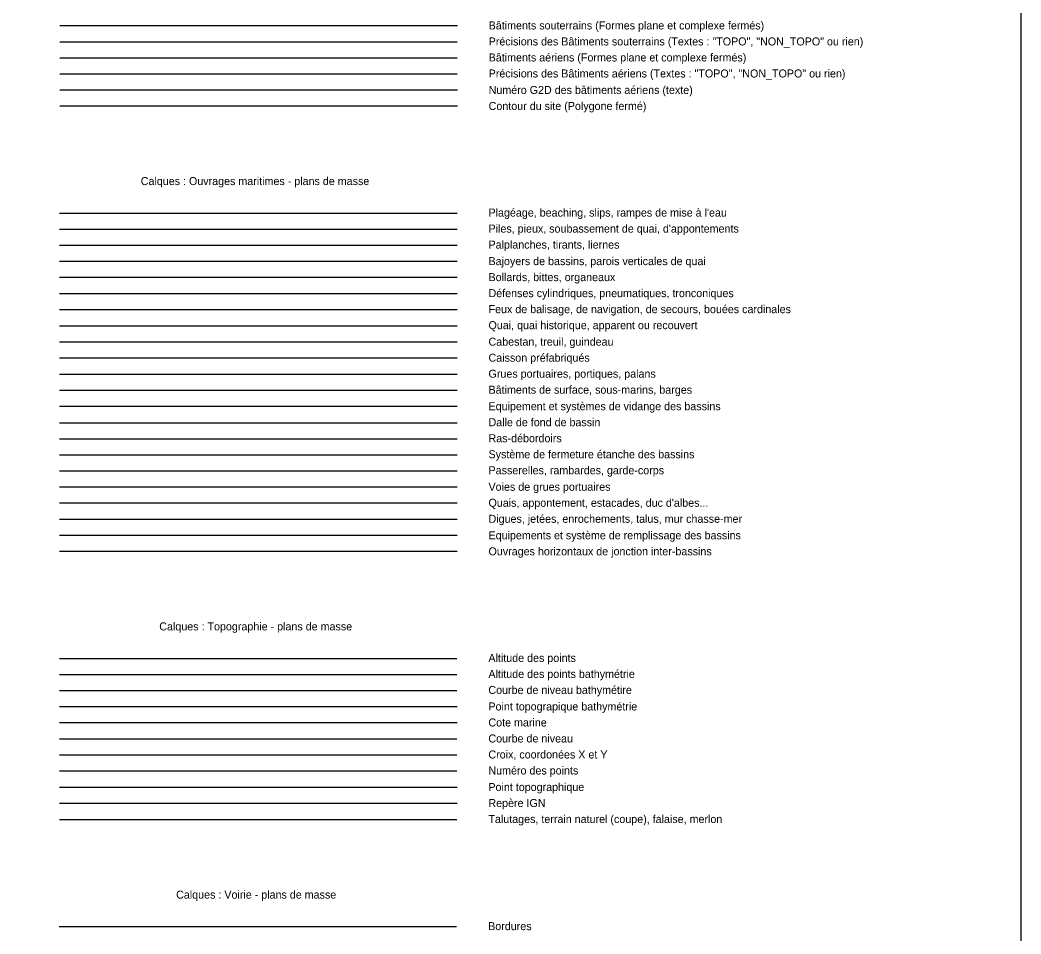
# Model space of a CAD drawing. Extents: x 703432 to 707394, y 7057985 to 7059523.
# Drawn here: x 707262 to 707324.5, y 7058477.4 to 7058534.5 of the extents above; entities that cross this region are included whole.
import ezdxf

# ---------------------------------------------------------------- set-up
doc = ezdxf.new("R2010")
doc.units = 0
for name, color, linetype in [('DH_CADRE -CARTOUCHE', 7, 'Continuous'), ('GEOSID_BATI_AERIEN _POLYGONE', 7, 'Continuous'), ('GEOSID_BATI_AERIEN_NUMERO', 7, 'Continuous'), ('GEOSID_BATI_AERIEN_PRECISION', 7, 'Continuous'), ('GEOSID_BATI_SOUTERRAIN_POLYGONE', 7, 'Continuous'), ('GEOSID_BATI_SOUTERRAIN_PRECISION', 7, 'Continuous'), ('GEOSID_SITE_POLYGONE', 7, 'Continuous'), ('OM_BAJOYER', 7, 'Continuous'), ('OM_BATEAU PORTE', 7, 'Continuous'), ('OM_BOLLARDS', 7, 'Continuous'), ('OM_CABESTAN', 7, 'Continuous'), ('OM_CAISSON PREFA', 7, 'Continuous'), ('OM_CONSTRUCTION METAL', 7, 'Continuous'), ('OM_DEFENSE D ACCOSTAGE', 7, 'Continuous'), ('OM_EQUIP DE LEVAGE', 7, 'Continuous'), ('OM_GALERIE REFOULEMENT', 7, 'Continuous'), ('OM_NAVIRE', 7, 'Continuous'), ('OM_OUVRAGES DE PROTECTION', 7, 'Continuous'), ('OM_OUVRAGES D’ACCOSTAGE', 7, 'Continuous'), ('OM_PAL TIR LIER', 7, 'Continuous'), ('OM_PLAGEAGE', 7, 'Continuous'), ('OM_QUAI', 7, 'Continuous'), ('OM_RADIER', 7, 'Continuous'), ('OM_RAS DEBORDOIR', 7, 'Continuous'), ('OM_SIGNAL NAUTIQUE', 7, 'Continuous'), ('OM_SOUBASSEMENT', 7, 'Continuous'), ('OM_STATION DE POMPAGE', 7, 'Continuous'), ('OM_TERRE-PLEINS', 7, 'Continuous'), ('OM_VOIES DE GRUES', 7, 'Continuous'), ('TOPO_ALT POINT', 7, 'Continuous'), ('TOPO_BATHY ALT COURBE NIVEAU', 7, 'Continuous'), ('TOPO_BATHY ALT POINT', 7, 'Continuous'), ('TOPO_BATHYMETRIE', 7, 'Continuous'), ('TOPO_COTE MARINE', 7, 'Continuous'), ('TOPO_COURBE NIVEAU', 7, 'Continuous'), ('TOPO_CROIX COORDONNEE', 7, 'Continuous'), ('TOPO_NUM POINT', 7, 'Continuous'), ('TOPO_POINT', 7, 'Continuous'), ('TOPO_REPERE IGN', 7, 'Continuous'), ('TOPO_TALUS-TERRAIN', 7, 'Continuous'), ('VOIRIE BORDURE', 7, 'Continuous')]:
    doc.layers.add(name, color=color, linetype=linetype)

msp = doc.modelspace()

# ---------------------------------------------------------------- linework, layer by layer
at = {"layer": 'DH_CADRE -CARTOUCHE'}
msp.add_lwpolyline([(707199.469, 7058644.551), (707324.469, 7058644.551), (707324.469, 7058419.551), (707199.469, 7058419.551)], close=True, dxfattribs=at)
at = {"layer": 'GEOSID_BATI_AERIEN _POLYGONE'}
msp.add_line((707264.447, 7058532.128), (707289.262, 7058532.128), dxfattribs=at)
at = {"layer": 'GEOSID_BATI_AERIEN_NUMERO'}
msp.add_line((707264.447, 7058530.128), (707289.276, 7058530.128), dxfattribs=at)
at = {"layer": 'GEOSID_BATI_AERIEN_PRECISION'}
msp.add_line((707264.447, 7058531.128), (707289.262, 7058531.128), dxfattribs=at)
at = {"layer": 'GEOSID_BATI_SOUTERRAIN_POLYGONE'}
msp.add_line((707264.447, 7058534.159), (707289.276, 7058534.159), dxfattribs=at)
at = {"layer": 'GEOSID_BATI_SOUTERRAIN_PRECISION'}
msp.add_line((707264.447, 7058533.128), (707289.262, 7058533.128), dxfattribs=at)
at = {"layer": 'GEOSID_SITE_POLYGONE'}
msp.add_line((707264.447, 7058529.128), (707289.276, 7058529.128), dxfattribs=at)
at = {"layer": 'OM_BAJOYER'}
msp.add_line((707264.439, 7058519.438), (707289.269, 7058519.438), dxfattribs=at)
at = {"layer": 'OM_BATEAU PORTE'}
msp.add_line((707264.439, 7058507.345), (707289.269, 7058507.345), dxfattribs=at)
at = {"layer": 'OM_BOLLARDS'}
msp.add_line((707264.439, 7058518.438), (707289.269, 7058518.438), dxfattribs=at)
at = {"layer": 'OM_CABESTAN'}
msp.add_line((707264.439, 7058514.407), (707289.269, 7058514.407), dxfattribs=at)
at = {"layer": 'OM_CAISSON PREFA'}
msp.add_line((707264.439, 7058513.407), (707289.269, 7058513.407), dxfattribs=at)
at = {"layer": 'OM_CONSTRUCTION METAL'}
msp.add_line((707264.439, 7058506.345), (707289.254, 7058506.345), dxfattribs=at)
at = {"layer": 'OM_DEFENSE D ACCOSTAGE'}
msp.add_line((707264.439, 7058517.407), (707289.254, 7058517.407), dxfattribs=at)
at = {"layer": 'OM_EQUIP DE LEVAGE'}
msp.add_line((707264.439, 7058512.376), (707289.254, 7058512.376), dxfattribs=at)
at = {"layer": 'OM_GALERIE REFOULEMENT'}
msp.add_line((707264.439, 7058510.376), (707289.269, 7058510.376), dxfattribs=at)
at = {"layer": 'OM_NAVIRE'}
msp.add_line((707264.439, 7058511.376), (707289.269, 7058511.376), dxfattribs=at)
at = {"layer": 'OM_OUVRAGES DE PROTECTION'}
msp.add_line((707264.439, 7058503.314), (707289.254, 7058503.314), dxfattribs=at)
at = {"layer": 'OM_OUVRAGES D’ACCOSTAGE'}
msp.add_line((707264.439, 7058504.345), (707289.269, 7058504.345), dxfattribs=at)
at = {"layer": 'OM_PAL TIR LIER'}
msp.add_line((707264.439, 7058520.438), (707289.254, 7058520.438), dxfattribs=at)
at = {"layer": 'OM_PLAGEAGE'}
msp.add_line((707264.439, 7058522.438), (707289.254, 7058522.438), dxfattribs=at)
at = {"layer": 'OM_QUAI'}
msp.add_line((707264.439, 7058515.407), (707289.254, 7058515.407), dxfattribs=at)
at = {"layer": 'OM_RADIER'}
msp.add_line((707264.439, 7058509.345), (707289.254, 7058509.345), dxfattribs=at)
at = {"layer": 'OM_RAS DEBORDOIR'}
msp.add_line((707264.439, 7058508.345), (707289.269, 7058508.345), dxfattribs=at)
at = {"layer": 'OM_SIGNAL NAUTIQUE'}
msp.add_line((707264.439, 7058516.407), (707289.254, 7058516.407), dxfattribs=at)
at = {"layer": 'OM_SOUBASSEMENT'}
msp.add_line((707264.439, 7058521.438), (707289.254, 7058521.438), dxfattribs=at)
at = {"layer": 'OM_STATION DE POMPAGE'}
msp.add_line((707264.439, 7058502.314), (707289.269, 7058502.314), dxfattribs=at)
at = {"layer": 'OM_TERRE-PLEINS'}
msp.add_line((707264.439, 7058501.314), (707289.269, 7058501.314), dxfattribs=at)
at = {"layer": 'OM_VOIES DE GRUES'}
msp.add_line((707264.439, 7058505.345), (707289.269, 7058505.345), dxfattribs=at)
at = {"layer": 'TOPO_ALT POINT'}
msp.add_line((707264.432, 7058494.624), (707289.247, 7058494.624), dxfattribs=at)
at = {"layer": 'TOPO_BATHY ALT COURBE NIVEAU'}
msp.add_line((707264.432, 7058492.624), (707289.247, 7058492.624), dxfattribs=at)
at = {"layer": 'TOPO_BATHY ALT POINT'}
msp.add_line((707264.432, 7058493.624), (707289.247, 7058493.624), dxfattribs=at)
at = {"layer": 'TOPO_BATHYMETRIE'}
msp.add_line((707264.432, 7058491.624), (707289.262, 7058491.624), dxfattribs=at)
at = {"layer": 'TOPO_COTE MARINE'}
msp.add_line((707264.432, 7058490.624), (707289.262, 7058490.624), dxfattribs=at)
at = {"layer": 'TOPO_COURBE NIVEAU'}
msp.add_line((707264.432, 7058489.593), (707289.247, 7058489.593), dxfattribs=at)
at = {"layer": 'TOPO_CROIX COORDONNEE'}
msp.add_line((707264.432, 7058488.593), (707289.247, 7058488.593), dxfattribs=at)
at = {"layer": 'TOPO_NUM POINT'}
msp.add_line((707264.432, 7058487.593), (707289.247, 7058487.593), dxfattribs=at)
at = {"layer": 'TOPO_POINT'}
msp.add_line((707264.432, 7058486.593), (707289.262, 7058486.593), dxfattribs=at)
at = {"layer": 'TOPO_REPERE IGN'}
msp.add_line((707264.432, 7058485.593), (707289.262, 7058485.593), dxfattribs=at)
at = {"layer": 'TOPO_TALUS-TERRAIN'}
msp.add_line((707264.432, 7058484.562), (707289.247, 7058484.562), dxfattribs=at)
at = {"layer": 'VOIRIE BORDURE'}
msp.add_line((707264.417, 7058477.872), (707289.232, 7058477.872), dxfattribs=at)

# ---------------------------------------------------------------- texts
at = {"layer": 'DH_CADRE -CARTOUCHE'}
for s, p in [(' Calques : Ouvrages maritimes - plans de masse', (707269.322, 7058524.188)), (' Calques : Topographie - plans de masse', (707270.478, 7058496.374)), (' Calques : Voirie - plans de masse', (707271.531, 7058479.622))]:
    msp.add_text(s, height=0.5, dxfattribs=at).set_placement(p)
at = {"layer": 'GEOSID_BATI_AERIEN _POLYGONE'}
msp.add_text('Bâtiments aériens (Formes plane et complexe fermés)', height=0.5, dxfattribs=at).set_placement((707291.23, 7058531.909))
at = {"layer": 'GEOSID_BATI_AERIEN_NUMERO'}
msp.add_text('Numéro G2D des bâtiments aériens (texte)', height=0.5, dxfattribs=at).set_placement((707291.23, 7058529.878))
at = {"layer": 'GEOSID_BATI_AERIEN_PRECISION'}
msp.add_text('Précisions des Bâtiments aériens (Textes : "TOPO", "NON_TOPO" ou rien)', height=0.5, dxfattribs=at).set_placement((707291.23, 7058530.909))
at = {"layer": 'GEOSID_BATI_SOUTERRAIN_POLYGONE'}
msp.add_text('Bâtiments souterrains (Formes plane et complexe fermés)', height=0.5, dxfattribs=at).set_placement((707291.23, 7058533.909))
at = {"layer": 'GEOSID_BATI_SOUTERRAIN_PRECISION'}
msp.add_text('Précisions des Bâtiments souterrains (Textes : "TOPO", "NON_TOPO" ou rien)', height=0.5, dxfattribs=at).set_placement((707291.23, 7058532.909))
at = {"layer": 'GEOSID_SITE_POLYGONE'}
msp.add_text('Contour du site (Polygone fermé)', height=0.5, dxfattribs=at).set_placement((707291.23, 7058528.878))
at = {"layer": 'OM_BAJOYER'}
msp.add_text('Bajoyers de bassins, parois verticales de quai', height=0.5, dxfattribs=at).set_placement((707291.222, 7058519.188))
at = {"layer": 'OM_BATEAU PORTE'}
msp.add_text('Système de fermeture étanche des bassins', height=0.5, dxfattribs=at).set_placement((707291.222, 7058507.126))
at = {"layer": 'OM_BOLLARDS'}
msp.add_text('Bollards, bittes, organeaux', height=0.5, dxfattribs=at).set_placement((707291.222, 7058518.188))
at = {"layer": 'OM_CABESTAN'}
msp.add_text('Cabestan, treuil, guindeau', height=0.5, dxfattribs=at).set_placement((707291.222, 7058514.157))
at = {"layer": 'OM_CAISSON PREFA'}
msp.add_text('Caisson préfabriqués', height=0.5, dxfattribs=at).set_placement((707291.222, 7058513.157))
at = {"layer": 'OM_CONSTRUCTION METAL'}
msp.add_text('Passerelles, rambardes, garde-corps', height=0.5, dxfattribs=at).set_placement((707291.222, 7058506.126))
at = {"layer": 'OM_DEFENSE D ACCOSTAGE'}
msp.add_text('Défenses cylindriques, pneumatiques, tronconiques', height=0.5, dxfattribs=at).set_placement((707291.222, 7058517.188))
at = {"layer": 'OM_EQUIP DE LEVAGE'}
msp.add_text('Grues portuaires, portiques, palans', height=0.5, dxfattribs=at).set_placement((707291.222, 7058512.157))
at = {"layer": 'OM_GALERIE REFOULEMENT'}
msp.add_text('Equipement et systèmes de vidange des bassins', height=0.5, dxfattribs=at).set_placement((707291.222, 7058510.126))
at = {"layer": 'OM_NAVIRE'}
msp.add_text('Bâtiments de surface, sous-marins, barges', height=0.5, dxfattribs=at).set_placement((707291.222, 7058511.157))
at = {"layer": 'OM_OUVRAGES DE PROTECTION'}
msp.add_text('Digues, jetées, enrochements, talus, mur chasse-mer', height=0.5, dxfattribs=at).set_placement((707291.222, 7058503.095))
at = {"layer": 'OM_OUVRAGES D’ACCOSTAGE'}
msp.add_text("Quais, appontement, estacades, duc d'albes...", height=0.5, dxfattribs=at).set_placement((707291.222, 7058504.095))
at = {"layer": 'OM_PAL TIR LIER'}
msp.add_text('Palplanches, tirants, liernes', height=0.5, dxfattribs=at).set_placement((707291.222, 7058520.219))
at = {"layer": 'OM_PLAGEAGE'}
msp.add_text("Plagéage, beaching, slips, rampes de mise à l'eau", height=0.5, dxfattribs=at).set_placement((707291.222, 7058522.219))
at = {"layer": 'OM_QUAI'}
msp.add_text('Quai, quai historique, apparent ou recouvert', height=0.5, dxfattribs=at).set_placement((707291.222, 7058515.188))
at = {"layer": 'OM_RADIER'}
msp.add_text('Dalle de fond de bassin', height=0.5, dxfattribs=at).set_placement((707291.222, 7058509.126))
at = {"layer": 'OM_RAS DEBORDOIR'}
msp.add_text('Ras-débordoirs', height=0.5, dxfattribs=at).set_placement((707291.222, 7058508.126))
at = {"layer": 'OM_SIGNAL NAUTIQUE'}
msp.add_text('Feux de balisage, de navigation, de secours, bouées cardinales', height=0.5, dxfattribs=at).set_placement((707291.222, 7058516.188))
at = {"layer": 'OM_SOUBASSEMENT'}
msp.add_text("Piles, pieux, soubassement de quai, d'appontements", height=0.5, dxfattribs=at).set_placement((707291.222, 7058521.219))
at = {"layer": 'OM_STATION DE POMPAGE'}
msp.add_text('Equipements et système de remplissage des bassins', height=0.5, dxfattribs=at).set_placement((707291.222, 7058502.064))
at = {"layer": 'OM_TERRE-PLEINS'}
msp.add_text('Ouvrages horizontaux de jonction inter-bassins', height=0.5, dxfattribs=at).set_placement((707291.222, 7058501.064))
at = {"layer": 'OM_VOIES DE GRUES'}
msp.add_text('Voies de grues portuaires', height=0.5, dxfattribs=at).set_placement((707291.222, 7058505.095))
at = {"layer": 'TOPO_ALT POINT'}
msp.add_text('Altitude des points', height=0.5, dxfattribs=at).set_placement((707291.215, 7058494.405))
at = {"layer": 'TOPO_BATHY ALT COURBE NIVEAU'}
msp.add_text('Courbe de niveau bathymétire', height=0.5, dxfattribs=at).set_placement((707291.215, 7058492.405))
at = {"layer": 'TOPO_BATHY ALT POINT'}
msp.add_text('Altitude des points bathymétrie', height=0.5, dxfattribs=at).set_placement((707291.215, 7058493.405))
at = {"layer": 'TOPO_BATHYMETRIE'}
msp.add_text('Point topograpique bathymétrie', height=0.5, dxfattribs=at).set_placement((707291.215, 7058491.374))
at = {"layer": 'TOPO_COTE MARINE'}
msp.add_text('Cote marine', height=0.5, dxfattribs=at).set_placement((707291.215, 7058490.374))
at = {"layer": 'TOPO_COURBE NIVEAU'}
msp.add_text('Courbe de niveau', height=0.5, dxfattribs=at).set_placement((707291.215, 7058489.374))
at = {"layer": 'TOPO_CROIX COORDONNEE'}
msp.add_text('Croix, coordonées X et Y', height=0.5, dxfattribs=at).set_placement((707291.215, 7058488.374))
at = {"layer": 'TOPO_NUM POINT'}
msp.add_text('Numéro des points', height=0.5, dxfattribs=at).set_placement((707291.215, 7058487.374))
at = {"layer": 'TOPO_POINT'}
msp.add_text('Point topographique', height=0.5, dxfattribs=at).set_placement((707291.215, 7058486.343))
at = {"layer": 'TOPO_REPERE IGN'}
msp.add_text('Repère IGN', height=0.5, dxfattribs=at).set_placement((707291.215, 7058485.343))
at = {"layer": 'TOPO_TALUS-TERRAIN'}
msp.add_text('Talutages, terrain naturel (coupe), falaise, merlon', height=0.5, dxfattribs=at).set_placement((707291.215, 7058484.343))
at = {"layer": 'VOIRIE BORDURE'}
msp.add_text('Bordures', height=0.5, dxfattribs=at).set_placement((707291.2, 7058477.653))

doc.saveas('drawing.dxf')
